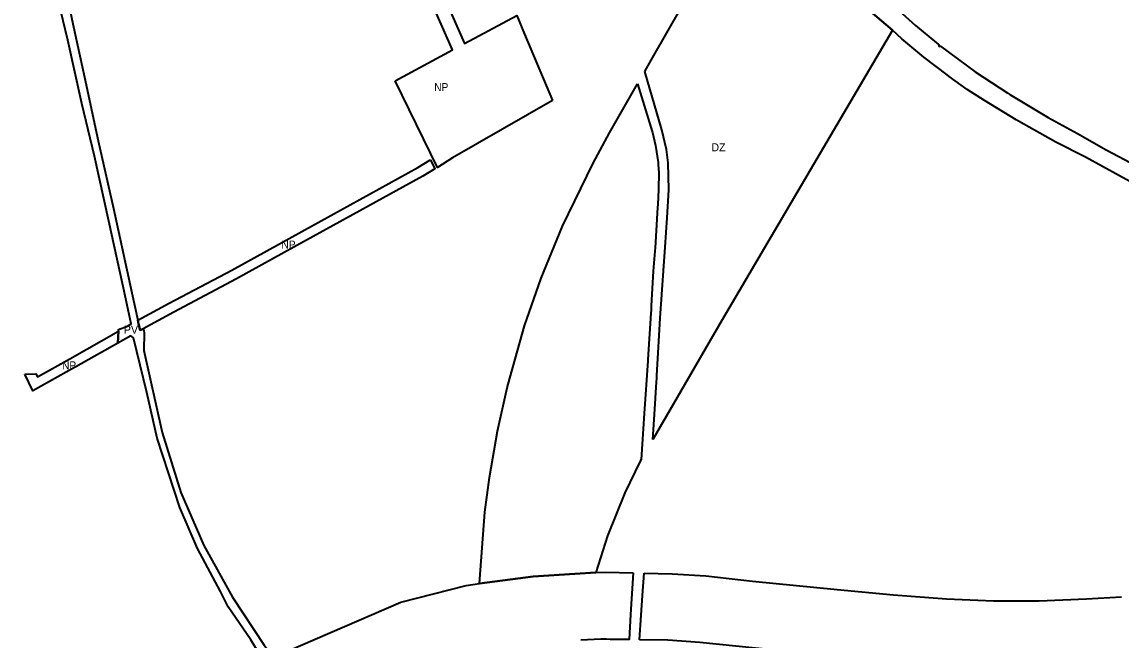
# Model space of a CAD drawing. Extents: x -650971 to -642489, y -1074311 to -1062745.
# Drawn here: x -648725 to -647077, y -1069053 to -1068126 of the extents above; entities that cross this region are included whole.
import ezdxf

# ---------------------------------------------------------------- set-up
doc = ezdxf.new("R2010")
doc.units = 0
doc.header["$LTSCALE"] = 4.8
for name, color, linetype, lineweight in [('15', 7, 'Continuous', 35), ('24', 7, 'Continuous', 35), ('25', 7, 'Continuous', 35), ('48', 7, 'Continuous', 35), ('62', 7, 'Continuous', 35)]:
    doc.layers.add(name, color=color, linetype=linetype, lineweight=lineweight)

msp = doc.modelspace()

# ---------------------------------------------------------------- linework, layer by layer
at = {"layer": '15'}
for points in [[(-648580.062, -1068590.087), (-648579.97, -1068587.39), (-648566.33, -1068582.22), (-648561.032, -1068578.982), (-648572.95, -1068522.97), (-648573.96, -1068518.34), (-648594.38, -1068425.02), (-648615.87, -1068327.3), (-648634.84, -1068248.76), (-648655.88, -1068153.63), (-648662.71, -1068124.76), (-648677.61, -1068061.74), (-648700.16, -1067963.42), (-648722.09, -1067863.84), (-648727.05, -1067844.33), (-648738.7, -1067792.04), (-648749.97, -1067741.49), (-648767.84, -1067652.98), (-648791.68, -1067543.78), (-648792.97, -1067537.86), (-648804.08, -1067534.88), (-648813.94, -1067506.27), (-648827.86, -1067465.86)], [(-648668.92, -1068032.96), (-648651.89, -1068111.95), (-648649.74, -1068121.95), (-648644.73, -1068145.27), (-648630.99, -1068209.19), (-648610.14, -1068304.32), (-648587.39, -1068405.82), (-648559.91, -1068532.62), (-648551.041, -1068573.16)], [(-648551.041, -1068573.16), (-648549.84, -1068578.65), (-648547.25, -1068588.14), (-648542.93, -1068586.13)], [(-648542.93, -1068586.13), (-648541.74, -1068589.27), (-648541.25, -1068592.3)], [(-648557.4, -1068599.9), (-648559.44, -1068598.37), (-648561.49, -1068596.84), (-648580.66, -1068607.64), (-648580.062, -1068590.087)], [(-648362.06, -1069084.664), (-648381.44, -1069052.48), (-648415.29, -1069003.16), (-648419.78, -1068994.25), (-648427.21, -1068980.13), (-648461.22, -1068915.44), (-648488.09, -1068854.16), (-648521.92, -1068750.34), (-648537.29, -1068681.95), (-648557.4, -1068599.9)], [(-648541.25, -1068592.3), (-648541.89, -1068618.64), (-648514.35, -1068741.53), (-648486.25, -1068831.83), (-648451.76, -1068910.91), (-648409.15, -1068988.44), (-648361.43, -1069060.64), (-648347.522, -1069078.405), (-648362.06, -1069084.664)]]:
    msp.add_lwpolyline(points, dxfattribs=at)
at = {"layer": '24'}
for points in [[(-647419.74, -1068138.917), (-647419.713, -1068138.871), (-647472.338, -1068093.096), (-647553.628, -1067999.427), (-647618.773, -1067899.914)], [(-647405.026, -1068113.904), (-647385.13, -1068131.51), (-647353.81, -1068157.67), (-647350.6, -1068160.26), (-647349.59, -1068163.24), (-647347.74, -1068162.54), (-647295.47, -1068201.09), (-647246.8, -1068233.08), (-647243.39, -1068235.26), (-647186.26, -1068269.45), (-647142.41, -1068293.81), (-647099.2, -1068318.27), (-647053.75, -1068342.11)], [(-647032.91, -1068382.51), (-647079.16, -1068357.01), (-647130.29, -1068328.8), (-647174.56, -1068306.35), (-647230.83, -1068274.93), (-647234.11, -1068273.04), (-647281.64, -1068244.34), (-647307.39, -1068227.44), (-647334.62, -1068208.02), (-647337.74, -1068205.67), (-647372.38, -1068179.01), (-647405.71, -1068151.74), (-647419.74, -1068138.917)], [(-646562.49, -1068790.69), (-646575.28, -1068775.04), (-646583.98, -1068766.42), (-646592.53, -1068758.66), (-646601.86, -1068751.01), (-646613.44, -1068743.65), (-646617.991, -1068741.503), (-646673.05, -1068812.491), (-646741.85, -1068895.719), (-646782.784, -1068941.581), (-646829.104, -1068987.917), (-646880.163, -1069024.903), (-646929.186, -1069052.925), (-646978.92, -1069073.93), (-647065.688, -1069087.73), (-647123.648, -1069091.043), (-647197.498, -1069094.255), (-647270.522, -1069094.255), (-647344.902, -1069091.02), (-647426.417, -1069084.624), (-647511.94, -1069076.703), (-647708.401, -1069056.275), (-647756.441, -1069053.207), (-647798.631, -1069052.508)], [(-648038.596, -1068968.281), (-647958.168, -1068957.73), (-647895.901, -1068953.392), (-647864.531, -1068951.823)], [(-647864.531, -1068951.823), (-647850.043, -1068951.098), (-647808.28, -1068952.066)], [(-647808.28, -1068952.066), (-647812.34, -1069014.54), (-647814.401, -1069052.246), (-647842.888, -1069051.774), (-647848.615, -1069051.679)], [(-647798.631, -1069052.508), (-647796.13, -1069015.57), (-647794.21, -1068986.12), (-647792.01, -1068952.442)], [(-647792.01, -1068952.442), (-647749.978, -1068953.416), (-647699.561, -1068956.635), (-647629.424, -1068964.608), (-647502.412, -1068977.157), (-647417.895, -1068984.986), (-647338.816, -1068991.19), (-647268.348, -1068994.255), (-647199.672, -1068994.255), (-647128.674, -1068991.167), (-647076.422, -1068988.18)], [(-648347.522, -1069078.405), (-648156.739, -1068996.273), (-648058.764, -1068970.927), (-648038.746, -1068968.301), (-648038.596, -1068968.284), (-648038.596, -1068968.284), (-648038.596, -1068968.281)], [(-647848.615, -1069051.679), (-647856.541, -1069051.548), (-647886.615, -1069053.052)]]:
    msp.add_lwpolyline(points, dxfattribs=at)
at = {"layer": '25'}
for points in [[(-647791.055, -1068200.507), (-647781.346, -1068183.485), (-647618.773, -1067899.914)], [(-647618.773, -1067899.914), (-647553.628, -1067999.427), (-647472.338, -1068093.096), (-647419.713, -1068138.871), (-647419.74, -1068138.917)], [(-647419.74, -1068138.917), (-647675.054, -1068572.919), (-647778.95, -1068752.433)], [(-647778.95, -1068752.433), (-647776.5, -1068714.8), (-647773.4, -1068665.71), (-647773.08, -1068660.57), (-647772.85, -1068656.41), (-647770.94, -1068622.47), (-647768.02, -1068570.36), (-647760.22, -1068463.96), (-647757.41, -1068419.98), (-647754.99, -1068378.21), (-647756.09, -1068337.61), (-647758.45, -1068317.66), (-647765.22, -1068287.94), (-647791.055, -1068200.507)], [(-647988.607, -1068644.072), (-647971.074, -1068581.98), (-647946.187, -1068510.254), (-647914.339, -1068432.512), (-647868.214, -1068337.803), (-647843.6, -1068292.629), (-647801.797, -1068219.34)], [(-647801.797, -1068219.34), (-647780.07, -1068290.53), (-647779.55, -1068292.23), (-647774.94, -1068311.47), (-647771.05, -1068337.01), (-647770.81, -1068340.29), (-647769.92, -1068352.1), (-647770.12, -1068377.5), (-647771.47, -1068400.07), (-647771.74, -1068404.5), (-647775.52, -1068464.97), (-647775.82, -1068469.74), (-647778.24, -1068499.95), (-647781.13, -1068551.88), (-647781.55, -1068558.38), (-647781.85, -1068562.97), (-647786.32, -1068632.19), (-647786.47, -1068634.37), (-647791.77, -1068713.23), (-647796.173, -1068782.191)], [(-648038.596, -1068968.281), (-648030.73, -1068861.213), (-648023.914, -1068809.332), (-648011.775, -1068739.718), (-647997.27, -1068674.747), (-647990.625, -1068651.217), (-647988.607, -1068644.072)], [(-647796.173, -1068782.191), (-647797.632, -1068784.713), (-647820.883, -1068832.117), (-647846.989, -1068896.545), (-647864.531, -1068951.823)], [(-647864.531, -1068951.823), (-647895.901, -1068953.392), (-647958.168, -1068957.73), (-648038.596, -1068968.281)]]:
    msp.add_lwpolyline(points, dxfattribs=at)
at = {"layer": '48'}
for points in [[(-647980.561, -1067632.719), (-648103.298, -1067686.416), (-648137.869, -1067708.325), (-648215.115, -1067761.28), (-648232.676, -1067770.513), (-648061.329, -1068158.649), (-647982.969, -1068116.575), (-647971.35, -1068144.48), (-647929.45, -1068244.16)], [(-648165.28, -1068214.465), (-648079.002, -1068168.139), (-648256.499, -1067766.091)], [(-647929.45, -1068244.16), (-648079.33, -1068330.03), (-648101.42, -1068344.28), (-648165.28, -1068214.465)], [(-648551.041, -1068573.16), (-648503.768, -1068547.914), (-648410.111, -1068498.408), (-648305.242, -1068440.3), (-648131.034, -1068344.388), (-648112.92, -1068333.424), (-648112.198, -1068333.037)], [(-648112.198, -1068333.037), (-648105.49, -1068346.46), (-648123.53, -1068357.38), (-648297.99, -1068453.43), (-648402.97, -1068511.6), (-648496.73, -1068561.16), (-648542.93, -1068586.13)], [(-648542.93, -1068586.13), (-648547.25, -1068588.14), (-648549.84, -1068578.65), (-648551.041, -1068573.16)], [(-648720.238, -1068654.205), (-648703.816, -1068653.711), (-648701.568, -1068658.36), (-648653.034, -1068631.191), (-648580.062, -1068590.087), (-648580.66, -1068607.64)], [(-648580.66, -1068607.64), (-648643.65, -1068643.13), (-648645.69, -1068644.27), (-648708.14, -1068679.23), (-648720.238, -1068654.205)]]:
    msp.add_lwpolyline(points, dxfattribs=at)

# ---------------------------------------------------------------- texts
at = {"layer": '62', "width": 0.95}
for p in [(-648106.583, -1068230.041), (-648335.583, -1068466.041), (-648664.583, -1068647.041)]:
    msp.add_text('NP', height=12, dxfattribs=at).set_placement(p)
at = {"layer": '62'}
for s, p in [('DZ', (-647691.118, -1068320.225)), ('PV', (-648571.984, -1068593.692))]:
    msp.add_text(s, height=12, dxfattribs=at).set_placement(p)

doc.saveas('drawing.dxf')
